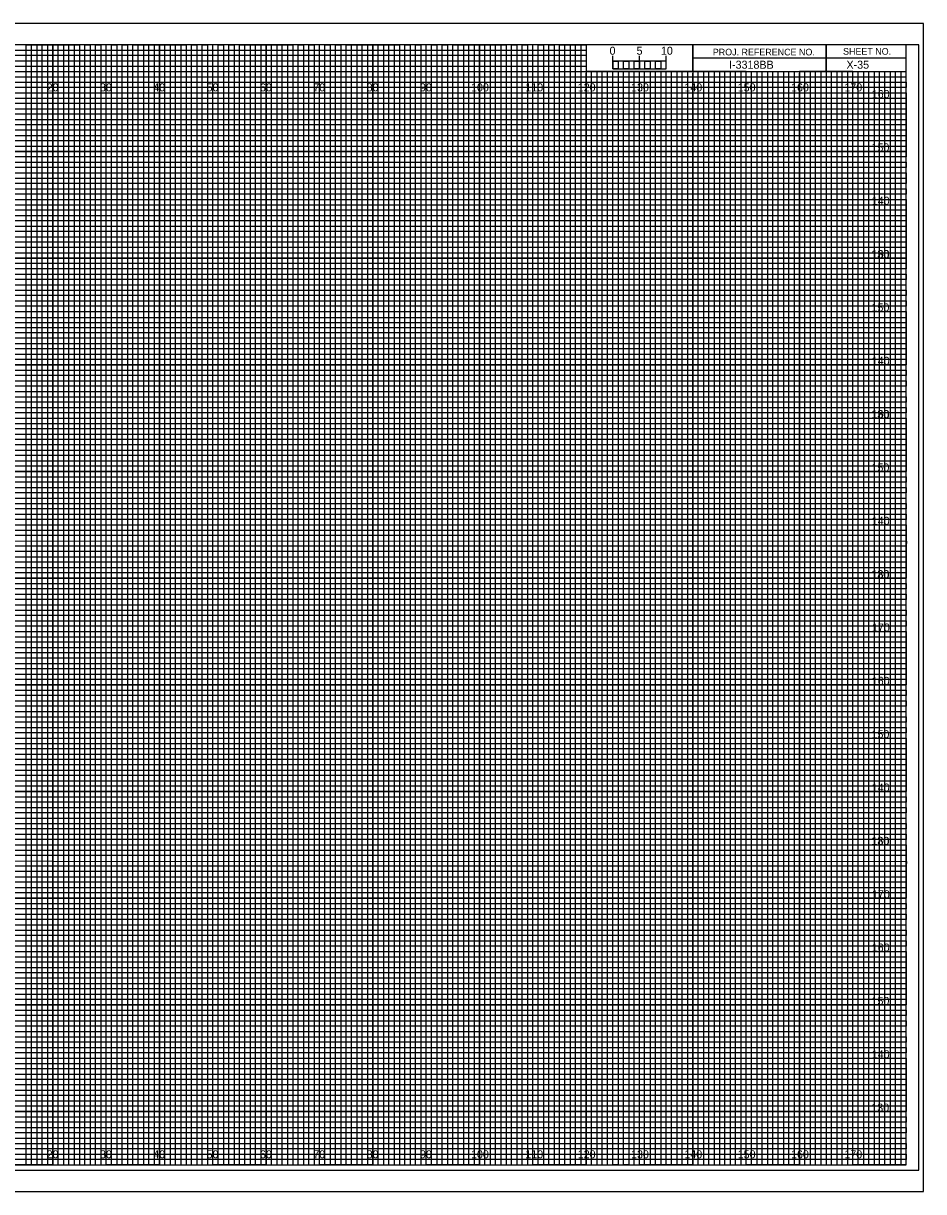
# Model space of a CAD drawing. Extents: x -13 to 323, y -5 to 214.
# Drawn here: x 154.5 to 323.3, y -5 to 214 of the extents above; entities that cross this region are included whole.
import ezdxf

# ---------------------------------------------------------------- set-up
doc = ezdxf.new("R2010")
doc.units = 0
for name, color, linetype in [('Exist Cross Section Cell', 7, 'Continuous'), ('Exist XS Center Line Elevation Label', 7, 'Continuous'), ('Exist XS Ground Line', 7, 'Continuous'), ('Prop CMT Guardrail Graphics', 7, 'Continuous'), ('Prop CMT Hydro Ditch Override', 7, 'Continuous'), ('Prop CMT Pvmt Course 1', 7, 'Continuous'), ('Prop CMT Pvmt Course 2', 7, 'Continuous'), ('Prop CMT Pvmt Surface', 7, 'Continuous'), ('Prop CMT Pvmt Surface Shoulder', 7, 'Continuous'), ('Prop CMT Shld Paved Course 1', 7, 'Continuous'), ('Prop CMT Shld Paved Course 2', 7, 'Continuous'), ('Prop CMT Slope Grass', 7, 'Continuous'), ('Prop CMT Subgrade Earthwork', 7, 'Continuous'), ('Prop XS Vertical Lines Alignments', 7, 'Continuous'), ('Scratch_Level_9', 7, 'Continuous')]:
    doc.layers.add(name, color=color, linetype=linetype)

msp = doc.modelspace()

# ---------------------------------------------------------------- linework, layer by layer
at = {"layer": 'Exist XS Center Line Elevation Label'}
for p, q in [((0, 209), (260, 209)), ((260, 209), (260, 207.98)), ((260, 207.98), (0, 207.98)), ((0, 207), (260, 207)), ((260, 205.89), (0, 205.89)), ((260, 207), (260, 205.89)), ((0, 204), (320, 204))]:
    msp.add_line(p, q, dxfattribs=at)
for points in [[(0, 203), (270, 203), (320, 203), (320, 202), (0, 202)], [(0, 201), (320, 201), (320, 199), (0, 199)], [(0, 198), (320, 198), (320, 197), (0, 196.98)], [(0, 196), (320, 196), (320, 194), (0, 194)], [(0, 193), (320, 193), (320, 192), (0, 192)], [(0, 191), (320, 191), (320, 189), (0, 189)], [(0, 188), (320, 188), (320, 187), (0, 187)], [(0, 186), (320, 186), (320, 184), (0, 184)], [(0, 183), (320, 183), (320, 182), (0, 182)], [(0, 181), (320, 181), (320, 179), (0, 179)], [(0, 178), (320, 178), (320, 177), (0, 177)], [(0, 176), (320, 176), (320, 173.95), (320, 173), (320, 172), (0, 172)], [(0, 174), (320, 174), (320, 173), (0, 173)], [(0, 171), (320, 171), (320, 169), (0, 169.03)], [(0, 169.03), (320, 169), (320, 168), (0, 168)], [(0, 167), (320, 167), (320, 166), (0, 166)], [(0, 164), (320, 164), (320, 163), (0, 163)], [(0, 162), (320, 162), (320, 161), (0, 161)], [(-0.07, 158.89), (320, 158.89), (320, 157.88), (-0.07, 157.88)], [(0, 157), (320, 157), (320, 156), (0, 156)], [(0, 154), (320, 154), (320, 153), (0, 153)], [(0, 152), (320, 152), (320, 151), (0, 151)], [(0, 149), (320, 149), (320, 148), (0, 148)], [(0, 147), (320, 147), (320, 146), (0, 146)], [(0, 144), (320, 144), (320, 143), (0, 143)], [(0, 142), (320, 142), (320, 141), (0, 141)], [(0, 139), (320, 139), (319.99, 137.98), (0, 138)], [(0, 137), (320, 137), (320, 136), (0, 136)], [(0, 134), (320, 134), (320, 133), (0, 133)], [(0, 132), (320, 132), (320, 131), (0, 131)], [(0, 129), (320, 129), (320, 128), (0, 128)], [(0, 127), (320, 127), (320, 126), (0, 126)], [(0, 124), (320, 124), (320, 123), (0, 123)], [(0, 122), (320, 122), (320, 121), (0, 121)], [(0, 119), (320, 119), (320, 118), (0, 118)], [(0, 116.99), (320.07, 116.91), (320, 116), (0, 116)], [(0, 114), (320, 114), (320, 113), (0, 113)], [(0, 112), (320, 112), (320, 111), (0, 111)], [(0, 109), (320, 109), (320, 108), (0, 108)], [(0, 107), (320, 107), (320, 106), (0, 106)], [(0, 104), (320, 104), (320, 103), (0, 103)], [(0, 102), (320, 102), (320, 101), (0, 101)], [(0, 99), (320, 99), (320, 98), (0, 98)], [(0, 97), (320, 97), (320, 96), (0, 96)], [(0, 94), (320, 94), (320, 93), (0, 93)], [(0, 92), (320, 92), (320, 91), (0, 91)], [(0, 89), (320, 89), (320, 88), (0, 88)], [(0, 87), (320, 87), (320, 86), (0, 86)], [(0, 84), (320, 84), (320, 83), (0, 83)], [(0, 82), (320, 82), (320, 81), (0, 81)], [(0, 79), (320, 79), (319.99, 77.98), (0, 78)], [(0, 77), (320, 77), (320, 76), (0, 76)], [(0, 74), (320, 74), (320, 73), (0, 73)], [(0, 72), (320, 72), (320, 71), (0, 71)], [(0, 69), (320, 69), (320, 68), (0, 68)], [(0, 67), (320, 67), (320, 66), (0, 66)], [(0, 64), (320, 64), (320, 63), (0, 63)], [(0, 62), (320, 62), (320, 61), (0, 61)], [(0, 59), (320, 59), (320, 58), (0, 58)], [(0, 56.99), (320.07, 56.91), (320, 56), (0, 56)], [(0, 54), (320, 54), (320, 53), (0, 53)], [(0, 52), (320, 52), (320, 51), (0, 51)], [(0, 49), (320, 49), (320, 48), (0, 48)], [(0, 47), (320, 47), (320, 46), (0, 46)], [(0, 44), (320, 44), (320, 43), (0, 43)], [(0, 42), (320, 42), (320, 41), (0, 41)], [(0, 39), (320, 39), (320, 38), (0, 38)], [(0, 37), (320, 37), (320, 36), (0, 36)], [(0, 34), (320, 34), (320, 33), (0, 33)], [(0, 32), (320, 32), (320, 31), (0, 31)], [(0, 29), (320, 29), (320, 28), (0, 28)], [(0, 27), (320, 27), (320, 26), (0, 26)], [(0, 24), (320, 24), (320, 23), (0, 23)], [(0, 22), (320, 22), (320, 21), (0, 21)], [(0, 19), (320, 19), (320, 18), (0, 18)], [(0, 17), (320, 17), (320, 16), (0, 16)], [(0, 14), (320, 14), (320, 13), (0, 13)], [(0, 12), (320, 12), (320, 11), (0, 11)], [(0, 9), (320, 9), (320, 8), (0, 8)], [(0, 7), (320, 7), (320, 6), (0, 6)], [(0, 4), (320, 4), (320, 3), (0, 3)], [(0, 2), (320, 2), (320, 1), (0, 1)]]:
    msp.add_lwpolyline(points, dxfattribs=at)
at = {"layer": 'Exist XS Ground Line'}
for points in [[(145, 0), (155, 0), (155, 210), (165, 210), (165, 0), (175, 0), (175, 210), (185, 210), (185, 0), (195, 0), (195, 210), (205, 210), (205, 0), (215, 0), (215, 210), (225, 210), (225, 0), (235, 0), (235, 210), (245, 210), (245, 0), (255, 0), (255, 210), (259.93, 210), (260, 210), (260, 205), (264.99, 205), (264.99, 0), (275, 0), (275, 205), (285, 205), (285, 0), (295, 0), (295, 205), (305, 205), (305, 0), (315, 0), (315, 205)], [(0, 205), (275, 205)], [(0, 185), (320, 185), (320, 195), (0, 195)], [(0, 165), (320, 165), (320, 175), (0, 175)], [(0, 145), (320, 145), (320, 155), (0, 155)], [(0, 125), (320, 125), (320, 135), (0, 135)], [(0, 105), (320, 105), (320, 115), (0, 115)], [(0, 85), (320, 85), (320, 95), (0, 95)], [(0, 65), (320, 65), (320, 75), (0, 75)], [(0, 45), (320, 45), (320, 55), (0, 55)], [(0, 25), (320, 25), (320, 35), (0, 35)], [(0, 5), (320, 5), (320, 15), (0, 15)]]:
    msp.add_lwpolyline(points, dxfattribs=at)
at = {"layer": 'Prop CMT Guardrail Graphics'}
msp.add_lwpolyline([(-10.8, -1), (322.4, -1), (322.4, 210), (-10.8, 210)], close=True, dxfattribs=at)
at = {"layer": 'Prop CMT Pvmt Course 1'}
for p, q in [((323.3, 214), (-13.4, 214)), ((-13.4, -5), (323.3, -5))]:
    msp.add_line(p, q, dxfattribs=at)
at = {"layer": 'Prop CMT Pvmt Surface'}
msp.add_lwpolyline([(-13.4, -5), (323.3, -5), (323.3, 214), (-13.4, 214)], close=True, dxfattribs=at)
at = {"layer": 'Prop CMT Pvmt Surface Shoulder'}
for p, q in [((160, 0), (160, 210)), ((170, 0), (170, 210)), ((180, 0), (180, 210)), ((190, 0), (190, 210)), ((200, 0), (200, 210)), ((210, 0), (210, 210)), ((220, 0), (220, 210)), ((230, 0), (230, 210)), ((240, 0), (240, 210)), ((250, 0), (250, 210)), ((260, 0), (260, 204.69)), ((270, 0), (270, 204.69)), ((280, 0), (280, 204.69)), ((290, 0), (290, 204.69)), ((300, 0), (300, 204.69)), ((310, 0), (310, 204.69)), ((0, 200), (320, 200)), ((0, 190), (320, 190)), ((0, 180), (320, 180)), ((0, 170), (320, 170)), ((0, 160), (320, 160)), ((0, 150), (320, 150)), ((0, 140), (320, 140)), ((0, 130), (320, 130)), ((0, 120), (320, 120)), ((0, 110), (320, 110)), ((0, 100), (320, 100)), ((0, 90), (320, 90)), ((0, 80), (320, 80)), ((0, 70), (320, 70)), ((0, 60), (320, 60)), ((0, 50), (320, 50)), ((0, 40), (320, 40)), ((0, 30), (320, 30)), ((0, 20), (320, 20)), ((0, 10), (320, 10))]:
    msp.add_line(p, q, dxfattribs=at)
at = {"layer": 'Prop CMT Shld Paved Course 1'}
for p, q in [((305, 210), (305, 205)), ((305, 205), (305, 210)), ((280, 207.5), (280, 205)), ((320, 207.49), (280, 207.49)), ((280, 205), (320, 205))]:
    msp.add_line(p, q, dxfattribs=at)
for points in [[(320, 210), (0, 210), (0, 0), (320, 0)], [(280, 210), (260, 210), (260, 205.03), (280, 205.03)], [(320, 210), (280, 210), (280, 205), (320, 205)]]:
    msp.add_lwpolyline(points, close=True, dxfattribs=at)
at = {"layer": 'Prop CMT Shld Paved Course 2'}
for p, q in [((267, 205), (266.01, 205)), ((266.01, 205), (266.01, 0)), ((267, 0), (267, 205)), ((269, 205), (268, 205)), ((268, 205), (268, 0)), ((269, 0), (269, 205)), ((266.01, 0), (265, 0)), ((268, 0), (267, 0))]:
    msp.add_line(p, q, dxfattribs=at)
for points in [[(155, 0), (156, 0), (156, 210), (157, 210), (157, 0)], [(157, 0), (158, 0), (158, 210), (159, 210), (159, 0)], [(160, 0), (161, 0), (161, 210), (162, 210), (162, 0)], [(162, 0), (163, 0), (163, 210), (164, 210), (164, 0)], [(165, 0), (166, 0), (166, 210), (167, 210), (167, 0)], [(167, 0), (168, 0), (168, 210), (169, 210), (169, 0)], [(170, 0), (171, 0), (171, 210), (172, 210), (172, 0)], [(172, 0), (173, 0), (173, 210), (174, 210), (174, 0)], [(175, 0), (176, 0), (176, 210), (177, 210), (177, 0)], [(177, 0), (178, 0), (178, 210), (179, 210), (179, 0)], [(180, 0), (181, 0), (181, 210), (182, 210), (182, 0)], [(182, 0), (183, 0), (183, 210), (184, 210), (184, 0)], [(185, 0), (186, 0), (186, 210), (187, 210), (187, 0)], [(187, 0), (188, 0), (188, 210), (189, 210), (189, 0)], [(190, 0), (191, 0), (191, 210), (192, 210), (192, 0)], [(192, 0), (193, 0), (193, 210), (194, 210), (194, 0)], [(195, 0), (196, 0), (196, 210), (197, 210), (197, 0)], [(197, 0), (198, 0), (198, 210), (199, 210), (199, 0)], [(200, 0), (201, 0), (201, 210), (202, 210), (202, 0)], [(202, 0), (203, 0), (203, 210), (204, 210), (204, 0)], [(205, 0), (206, 0), (206, 210), (207, 210), (207, 0)], [(207, 0), (208, 0), (208, 210), (209, 210), (209, 0)], [(210, 0), (211, 0), (211, 210), (212, 210), (212, 0)], [(212, 0), (213, 0), (213, 210), (214, 210), (214, 0)], [(215, 0), (216, 0), (216, 210), (217, 210), (217, 0)], [(217, 0), (218, 0), (218, 210), (219, 210), (219, 0)], [(220, 0), (221, 0), (221, 210), (222, 210), (222, 0)], [(222, 0), (223, 0), (223, 210), (224, 210), (224, 0)], [(225, 0), (226, 0), (226, 210), (227, 210), (227, 0)], [(227, 0), (228, 0), (228, 210), (229, 210), (229, 0)], [(230, 0), (231, 0), (231, 210), (232, 210), (232, 0)], [(232, 0), (233, 0), (233, 210), (234, 210), (234, 0)], [(235, 0), (236, 0), (236, 210), (237, 210), (237, 0)], [(237, 0), (238, 0), (238, 210), (239, 210), (239, 0)], [(240, 0), (241, 0), (241, 210), (242, 210), (242, 0)], [(242, 0), (243, 0), (243, 210), (244, 210), (244, 0)], [(245, 0), (246, 0), (246, 210), (247, 210), (247, 0)], [(247, 0), (248, 0), (248, 210), (249, 210), (249, 0)], [(250, 0), (251, 0), (251, 210), (252, 210), (252, 0)], [(252, 0), (253, 0), (253, 210), (254, 210), (254, 0)], [(255, 0), (256, 0), (256, 210), (257, 210), (257, 0)], [(257, 0), (258, 0), (258, 210), (259, 210), (259, 0)], [(260, 0), (261, 0), (261, 205), (262.02, 205), (262.02, 0)], [(262, 0), (263, 0), (263, 205), (263.99, 205), (263.99, 0)], [(270, 0), (270.98, 0), (270.98, 205), (272, 205), (272, 0)], [(272, 0), (273, 0), (273, 205), (274.05, 205), (274.05, 0)], [(275, 0), (276, 0), (276, 205), (277, 205), (277, 0)], [(277, 0), (278, 0), (278, 205), (279, 205), (279, 0)], [(280, 0), (281, 0), (281, 205), (282, 205), (282, 0)], [(282, 0), (283, 0), (283, 205), (284, 205), (284, 0)], [(285, 0), (286, 0), (286, 205), (287, 205), (287, 0)], [(287, 0), (288, 0), (288, 205), (289, 205), (289, 0)], [(290, 0), (291, 0), (291, 205), (292, 205), (292, 0)], [(292, 0), (293, 0), (293, 205), (294, 205), (294, 0)], [(295, 0), (296, 0), (296, 205), (297, 205), (297, 0)], [(297, 0), (298, 0), (298, 205), (299, 205), (299, 0)], [(300, 0), (301, 0), (301, 205), (302, 205), (302, 0)], [(302, 0), (303, 0), (303, 205), (304, 205), (304, 0)], [(305, 0), (306, 0), (306, 205), (307, 205), (307, 0)], [(307, 0), (308, 0), (308, 205), (309, 205), (309, 0)], [(310, 0), (311, 0), (311, 205), (312, 205), (312, 0)], [(312, 0), (313, 0), (313, 205), (314, 205), (314, 0)], [(315, 0), (316, 0), (316, 205), (317, 205), (317, 0)], [(317, 0), (318, 0), (318, 205), (319, 205), (319, 0)]]:
    msp.add_lwpolyline(points, dxfattribs=at)
at = {"layer": 'Prop CMT Subgrade Earthwork'}
for p, q in [((265, 205.49), (265, 207.9)), ((265, 206.9), (265, 207.9)), ((270, 205.49), (270, 207.9)), ((275, 205.49), (275, 207.9)), ((275, 206.9), (275, 207.9))]:
    msp.add_line(p, q, dxfattribs=at)
for points in [[(275, 206.9), (265, 206.9), (265, 205.49), (275, 205.49)], [(265, 206.9), (266, 206.9), (266, 205.49), (265, 205.49)], [(267, 206.9), (268, 206.9), (268, 205.49), (267, 205.49)], [(269, 206.9), (270, 206.9), (270, 205.49), (269, 205.49)], [(271, 206.9), (272, 206.9), (272, 205.49), (271, 205.49)], [(273, 206.9), (274, 206.9), (274, 205.49), (273, 205.49)]]:
    msp.add_lwpolyline(points, close=True, dxfattribs=at)
at = {"layer": 'Scratch_Level_9'}
for p, q in [((170, 210), (160, 210)), ((160, 210), (160, 0)), ((170, 0), (170, 210)), ((190, 210), (180, 210)), ((180, 210), (180, 0)), ((190, 0), (190, 210)), ((210, 210), (200, 210)), ((200, 210), (200, 0)), ((210, 0), (210, 210)), ((230, 210), (220, 210)), ((220, 210), (220, 0)), ((230, 0), (230, 210)), ((250, 210), (240, 210)), ((240, 210), (240, 0)), ((250, 0), (250, 210)), ((260, 210), (260, 0)), ((270, 0), (270, 205)), ((290, 205), (280, 205)), ((280, 205), (280, 0)), ((290, 0), (290, 205)), ((310, 205), (300, 205)), ((300, 205), (300, 0)), ((310, 0), (310, 205)), ((160, 0), (150, 0)), ((180, 0), (170, 0)), ((200, 0), (190, 0)), ((220, 0), (210, 0)), ((240, 0), (230, 0)), ((260, 0), (250, 0)), ((280, 0), (270, 0)), ((300, 0), (290, 0)), ((320, 0), (310, 0)), ((320, 0), (320, 0))]:
    msp.add_line(p, q, dxfattribs=at)
for points in [[(0, 200), (320, 200), (320, 190), (0, 190)], [(0, 180), (320, 180), (320, 170), (0, 170)], [(0, 160), (320, 160), (320, 150), (0, 150)], [(0, 140), (320, 140), (320, 130), (0, 130)], [(0, 120), (320, 120), (320, 110), (0, 110)], [(0, 100), (320, 100), (320, 90), (0, 90)], [(0, 80), (320, 80), (320, 70), (0, 70)], [(0, 60), (320, 60), (320, 50), (0, 50)], [(0, 40), (320, 40), (320, 30), (0, 30)], [(0, 20), (320, 20), (320, 10), (0, 10)]]:
    msp.add_lwpolyline(points, dxfattribs=at)

# ---------------------------------------------------------------- texts
at = {"layer": 'Exist Cross Section Cell'}
for s, p in [('20', (158.86, 201.25)), ('30', (168.86, 201.25)), ('40', (178.86, 201.25)), ('50', (188.86, 201.25)), ('60', (198.86, 201.25)), ('70', (208.86, 201.25)), ('80', (218.86, 201.25)), ('90', (228.86, 201.25)), ('100', (238.44, 201.25)), ('110', (248.62, 201.25)), ('120', (258.44, 201.25)), ('130', (268.44, 201.25)), ('140', (278.44, 201.25)), ('150', (288.44, 201.25)), ('160', (298.44, 201.25)), ('170', (308.44, 201.25)), ('20', (158.86, 1.25)), ('30', (168.86, 1.25)), ('40', (178.86, 1.25)), ('50', (188.86, 1.25)), ('60', (198.86, 1.25)), ('70', (208.86, 1.25)), ('80', (218.86, 1.25)), ('90', (228.86, 1.25)), ('100', (238.44, 1.25)), ('110', (248.62, 1.25)), ('120', (258.44, 1.25)), ('130', (268.44, 1.25)), ('140', (278.44, 1.25)), ('150', (288.44, 1.25)), ('160', (298.44, 1.25)), ('170', (308.44, 1.25))]:
    msp.add_text(s, height=1.5, dxfattribs=at).set_placement(p)
at = {"layer": 'Prop CMT Hydro Ditch Override'}
msp.add_text('I-3318BB', height=1.5, dxfattribs=at).set_placement((286.82, 205.5))
at = {"layer": 'Prop CMT Pvmt Course 2'}
for s, p in [('160', (313.57, 200)), ('150', (313.52, 190)), ('140', (313.57, 180)), ('130', (313.49, 170)), ('160', (313.57, 170)), ('150', (313.52, 160)), ('140', (313.57, 150)), ('130', (313.49, 140)), ('160', (313.57, 140)), ('150', (313.52, 130)), ('140', (313.57, 120)), ('130', (313.49, 110)), ('180', (313.55, 110)), ('170', (313.61, 100)), ('160', (313.57, 90)), ('150', (313.52, 80)), ('140', (313.57, 70)), ('130', (313.49, 60)), ('180', (313.55, 60)), ('170', (313.61, 50)), ('160', (313.57, 40)), ('150', (313.52, 30)), ('140', (313.57, 20)), ('130', (313.49, 10))]:
    msp.add_text(s, height=1.5, dxfattribs=at).set_placement(p)
at = {"layer": 'Prop CMT Shld Paved Course 1'}
for s, p in [('PROJ. REFERENCE NO.', (283.77, 207.99)), ('SHEET NO.', (308.19, 208.12))]:
    msp.add_text(s, height=1.25, dxfattribs=at).set_placement(p)
at = {"layer": 'Prop CMT Slope Grass'}
msp.add_text('X-35', height=1.5, dxfattribs=at).set_placement((308.83, 205.5))
at = {"layer": 'Prop CMT Subgrade Earthwork'}
msp.add_text('0', height=1.5, dxfattribs=at).set_placement((264.41, 208.12))
at = {"layer": 'Prop XS Vertical Lines Alignments'}
for s, p in [('5', (269.47, 208.12)), ('10', (274.04, 208.12))]:
    msp.add_text(s, height=1.5, dxfattribs=at).set_placement(p)

doc.saveas('drawing.dxf')
